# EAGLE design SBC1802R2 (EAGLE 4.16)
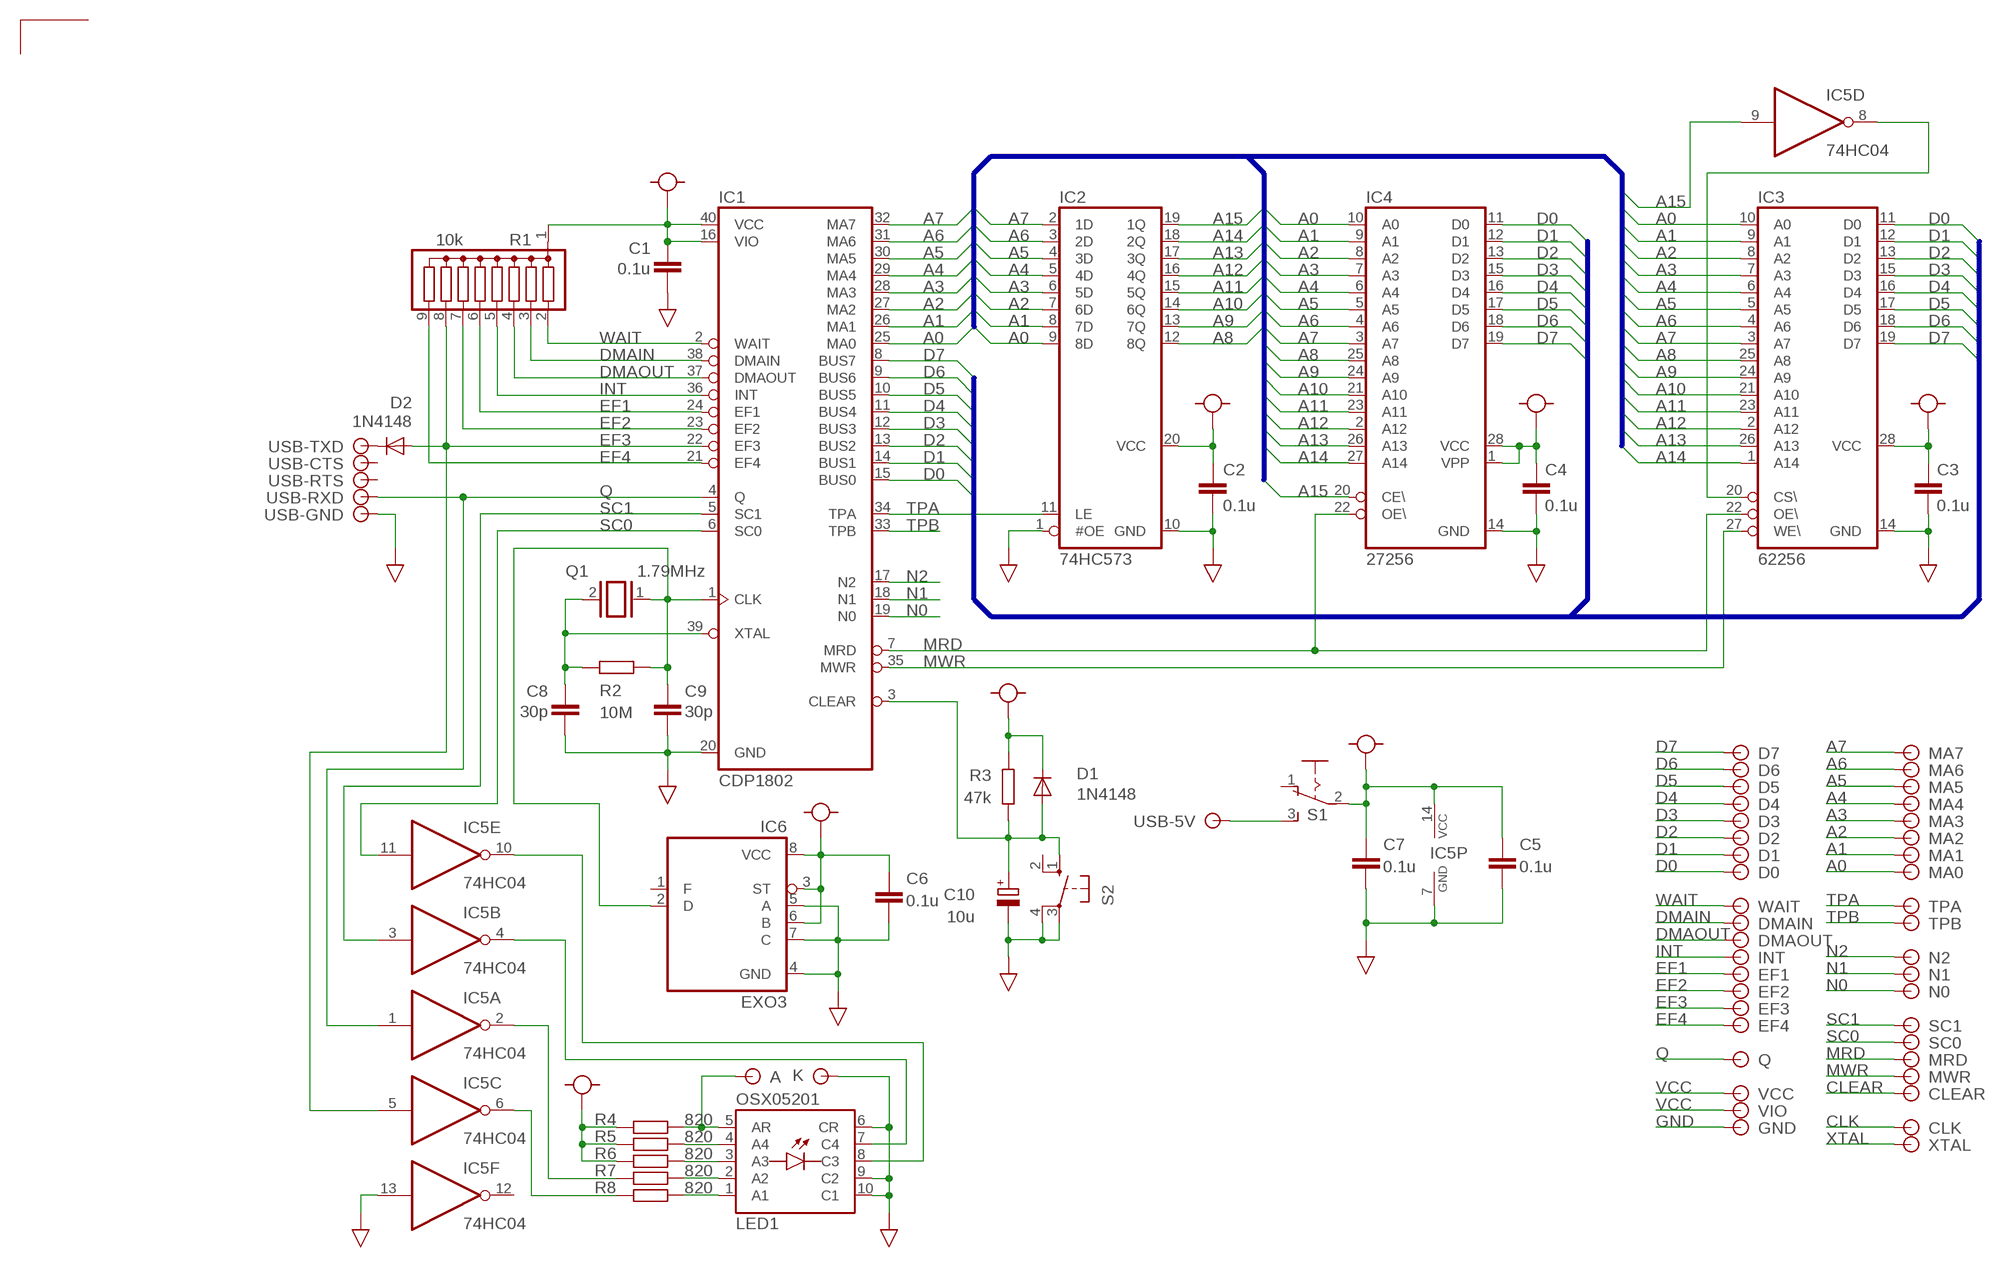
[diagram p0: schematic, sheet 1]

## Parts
C1  0.1u  C-CERAMIC  [C025-025X050]
C2  0.1u  C-CERAMIC  [C025-025X050]
C3  0.1u  C-CERAMIC  [C025-025X050]
C4  0.1u  C-CERAMIC  [C025-025X050]
C5  0.1u  C-CERAMIC  [C025-025X050]
C6  0.1u  C-CERAMIC  [C025-025X050]
C7  0.1u  C-CERAMIC  [C025-025X050]
C8  30p  C-CERAMIC  [C025-025X050]
C9  30p  C-CERAMIC  [C025-025X050]
C10  10u  C-TANTALUM  [C4518]
D1  1N4148  1S1588  [DO41-10]
D2  1N4148  1S1588  [DO41-10]
IC1  CDP1802  [DIL40]
IC2  74HC573  [DIL20]
IC3  62256  62256P  [DIL28]
IC4  27256  27256P  [DIL28]
IC5  74HC04  7404  [DIL14]
IC6  EXO3  EXO-3  [DIL08R]
LED1  OSX05201  OSX05201-GGR1  [OSX05201-GGR1]
Q1  1.79MHz  XTAL/S  [QS]
R1  10k  G08R  [SIL9]
R2  10M  R1/8W  [0207/10]
R3  47k  R1/8W  [0207/10]
R4  820  R1/8W  [0207/10]
R5  820  R1/8W  [0207/10]
R6  820  R1/8W  [0207/10]
R7  820  R1/8W  [0207/10]
R8  820  R1/8W  [0207/10]
S1  255SB  [255SB]
S2  SW-TACT  [B3F-10XX]
U$1  D7  LAND-NN-N  [LAND-NN-N]
U$2  MA7  LAND-NN-N  [LAND-NN-N]
U$3  D6  LAND-NN-N  [LAND-NN-N]
U$4  MA6  LAND-NN-N  [LAND-NN-N]
U$5  D5  LAND-NN-N  [LAND-NN-N]
U$6  MA5  LAND-NN-N  [LAND-NN-N]
U$7  D4  LAND-NN-N  [LAND-NN-N]
U$8  MA4  LAND-NN-N  [LAND-NN-N]
U$9  D3  LAND-NN-N  [LAND-NN-N]
U$10  MA3  LAND-NN-N  [LAND-NN-N]
U$11  D2  LAND-NN-N  [LAND-NN-N]
U$12  MA2  LAND-NN-N  [LAND-NN-N]
U$13  D1  LAND-NN-N  [LAND-NN-N]
U$14  MA1  LAND-NN-N  [LAND-NN-N]
U$15  D0  LAND-NN-N  [LAND-NN-N]
U$16  MA0  LAND-NN-N  [LAND-NN-N]
U$17  A  LAND-NN-N  [LAND-NN-N]
U$18  K  LAND-NN-N  [LAND-NN-N]
U$19  WAIT  LAND-NN-N  [LAND-NN-N]
U$20  TPA  LAND-NN-N  [LAND-NN-N]
U$21  DMAIN  LAND-NN-N  [LAND-NN-N]
U$22  TPB  LAND-NN-N  [LAND-NN-N]
U$23  DMAOUT  LAND-NN-N  [LAND-NN-N]
U$24  INT  LAND-NN-N  [LAND-NN-N]
U$25  N2  LAND-NN-N  [LAND-NN-N]
U$26  EF1  LAND-NN-N  [LAND-NN-N]
U$27  N1  LAND-NN-N  [LAND-NN-N]
U$28  EF2  LAND-NN-N  [LAND-NN-N]
U$29  N0  LAND-NN-N  [LAND-NN-N]
U$30  EF3  LAND-NN-N  [LAND-NN-N]
U$31  EF4  LAND-NN-N  [LAND-NN-N]
U$32  SC1  LAND-NN-N  [LAND-NN-N]
U$33  SC0  LAND-NN-N  [LAND-NN-N]
U$34  Q  LAND-NN-N  [LAND-NN-N]
U$35  MRD  LAND-NN-N  [LAND-NN-N]
U$36  MWR  LAND-NN-N  [LAND-NN-N]
U$37  VCC  LAND-NN-N  [LAND-NN-N]
U$38  CLEAR  LAND-NN-N  [LAND-NN-N]
U$39  VIO  LAND-NN-N  [LAND-NN-N]
U$40  GND  LAND-NN-N  [LAND-NN-N]
U$41  CLK  LAND-NN-N  [LAND-NN-N]
U$42  XTAL  LAND-NN-N  [LAND-NN-N]
USB-  TTL-232R-5V  [TTL-232R-5V]

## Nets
A0: IC1.25(MA0) IC2.9(8D) IC3.10(A0) IC4.10(A0) U$16.P
A1: IC1.26(MA1) IC2.8(7D) IC3.9(A1) IC4.9(A1) U$14.P
A2: IC1.27(MA2) IC2.7(6D) IC3.8(A2) IC4.8(A2) U$12.P
A3: IC1.28(MA3) IC2.6(5D) IC3.7(A3) IC4.7(A3) U$10.P
A4: IC1.29(MA4) IC2.5(4D) IC3.6(A4) IC4.6(A4) U$8.P
A5: IC1.30(MA5) IC2.4(3D) IC3.5(A5) IC4.5(A5) U$6.P
A6: IC1.31(MA6) IC2.3(2D) IC3.4(A6) IC4.4(A6) U$4.P
A7: IC1.32(MA7) IC2.2(1D) IC3.3(A7) IC4.3(A7) U$2.P
A8: IC2.12(8Q) IC3.25(A8) IC4.25(A8)
A9: IC2.13(7Q) IC3.24(A9) IC4.24(A9)
A10: IC2.14(6Q) IC3.21(A10) IC4.21(A10)
A11: IC2.15(5Q) IC3.23(A11) IC4.23(A11)
A12: IC2.16(4Q) IC3.2(A12) IC4.2(A12)
A13: IC2.17(3Q) IC3.26(A13) IC4.26(A13)
A14: IC2.18(2Q) IC3.1(A14) IC4.27(A14)
A15: IC2.19(1Q) IC4.20(CE\) IC5.9(D:I)
CLEAR: C10.+ D1.A IC1.3(CLEAR) R3.2 S2.1(S) U$38.P
CLK: C9.1 IC1.1(CLK) IC6.2(D) Q1.1 R2.2 U$41.P
D0: IC1.15(BUS0) IC3.11(D0) IC4.11(D0) U$15.P
D1: IC1.14(BUS1) IC3.12(D1) IC4.12(D1) U$13.P
D2: IC1.13(BUS2) IC3.13(D2) IC4.13(D2) U$11.P
D3: IC1.12(BUS3) IC3.15(D3) IC4.15(D3) U$9.P
D4: IC1.11(BUS4) IC3.16(D4) IC4.16(D4) U$7.P
D5: IC1.10(BUS5) IC3.17(D5) IC4.17(D5) U$5.P
D6: IC1.9(BUS6) IC3.18(D6) IC4.18(D6) U$3.P
D7: IC1.8(BUS7) IC3.19(D7) IC4.19(D7) U$1.P
DMAIN: IC1.38(DMAIN) R1.3 U$21.P
DMAOUT: IC1.37(DMAOUT) R1.4 U$23.P
EF1: IC1.24(EF1) R1.6 U$26.P
EF2: IC1.23(EF2) R1.7 U$28.P
EF3: D2.A IC1.22(EF3) IC5.5(C:I) R1.8 U$30.P
EF4: IC1.21(EF4) R1.9 U$31.P
GND: C1.2 C2.2 C3.2 C4.2 C5.2 C6.2 C7.2 C8.2 C9.2 C10.- IC1.20(GND) IC2.1(#OE) IC2.10(GND) IC3.14(GND) IC4.14(GND) IC5.7(P:GND) IC5.13(F:I) IC6.4(GND) IC6.5(A) IC6.7(C) LED1.6(CR) LED1.9(C2) LED1.10(C1) S2.3(P) S2.4(P1) U$18.P U$40.P USB-.1
INT: IC1.36(INT) R1.5 U$24.P
MRD: IC1.7(MRD) IC3.22(OE\) IC4.22(OE\) U$35.P
MWR: IC1.35(MWR) IC3.27(WE\) U$36.P
N0: IC1.19(N0) U$29.P
N1: IC1.18(N1) U$27.P
N2: IC1.17(N2) U$25.P
N$1: S1.3(S) USB-.3
N$2: LED1.5(AR) R4.2 U$17.P
N$3: IC5.6(C:O) R8.1
N$4: IC5.2(A:O) R7.1
N$5: IC5.10(E:O) LED1.8(C3)
N$6: IC5.4(B:O) LED1.7(C4)
N$7: LED1.4(A4) R5.2
N$8: LED1.3(A3) R6.2
N$9: D2.C USB-.4
N$13: IC3.20(CS\) IC5.8(D:O)
N$16: LED1.1(A1) R8.2
N$17: LED1.2(A2) R7.2
Q: IC1.4(Q) IC5.1(A:I) U$34.P USB-.5
SC0: IC1.6(SC0) IC5.11(E:I) U$33.P
SC1: IC1.5(SC1) IC5.3(B:I) U$32.P
TPA: IC1.34(TPA) IC2.11(LE) U$20.P
TPB: IC1.33(TPB) U$22.P
VCC: C1.1 C2.1 C3.1 C4.1 C5.1 C6.1 C7.1 D1.C IC1.16(VIO) IC1.40(VCC) IC2.20(VCC) IC3.28(VCC) IC4.1(VPP) IC4.28(VCC) IC5.14(P:VCC) IC6.3(ST) IC6.6(B) IC6.8(VCC) R1.1 R3.1 R4.1 R5.1 R6.1 S1.2(P) U$37.P U$39.P
WAIT: IC1.2(WAIT) R1.2 U$19.P
XTAL: C8.1 IC1.39(XTAL) Q1.2 R2.1 U$42.P
Unconnected: IC5.12(F:O) IC6.1(F) S1.1(O) S2.2(S1) USB-.2 USB-.6

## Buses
A[0..15]
D[0..7]

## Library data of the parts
C1-C9 = olimex-devices:C-CERAMIC: Ceramic Conenser
C10 = olimex-devices:C-TANTALUM: Tantalum Condenser
D1 D2 = olimex-devices:1S1588: Small Signal Diode
IC1 = olimex-devices:CDP1802
IC2 = olimex-devices:74HC573
IC3 = olimex-devices:62256P
IC4 = olimex-devices:27256P
IC5 = olimex-devices:7404: Hex INVERTER
IC6 = olimex-devices:EXO-3
LED1 = olimex-devices:OSX05201-GGR1
Q1 = olimex-devices:XTAL/S: X'tal Oscirator
R1 = olimex-devices:G08R: SIL RESISTOR
R2-R8 = olimex-devices:R1/8W: Carbon Resistor
S1 = olimex-devices:255SB: SLIDING SWITCH distributor Buerklin, 11G810
S2 = olimex-devices:SW-TACT: Tact Switch (Small)
U$1-U$42 = olimex-devices:LAND-NN-N
USB- = olimex-devices:TTL-232R-5V

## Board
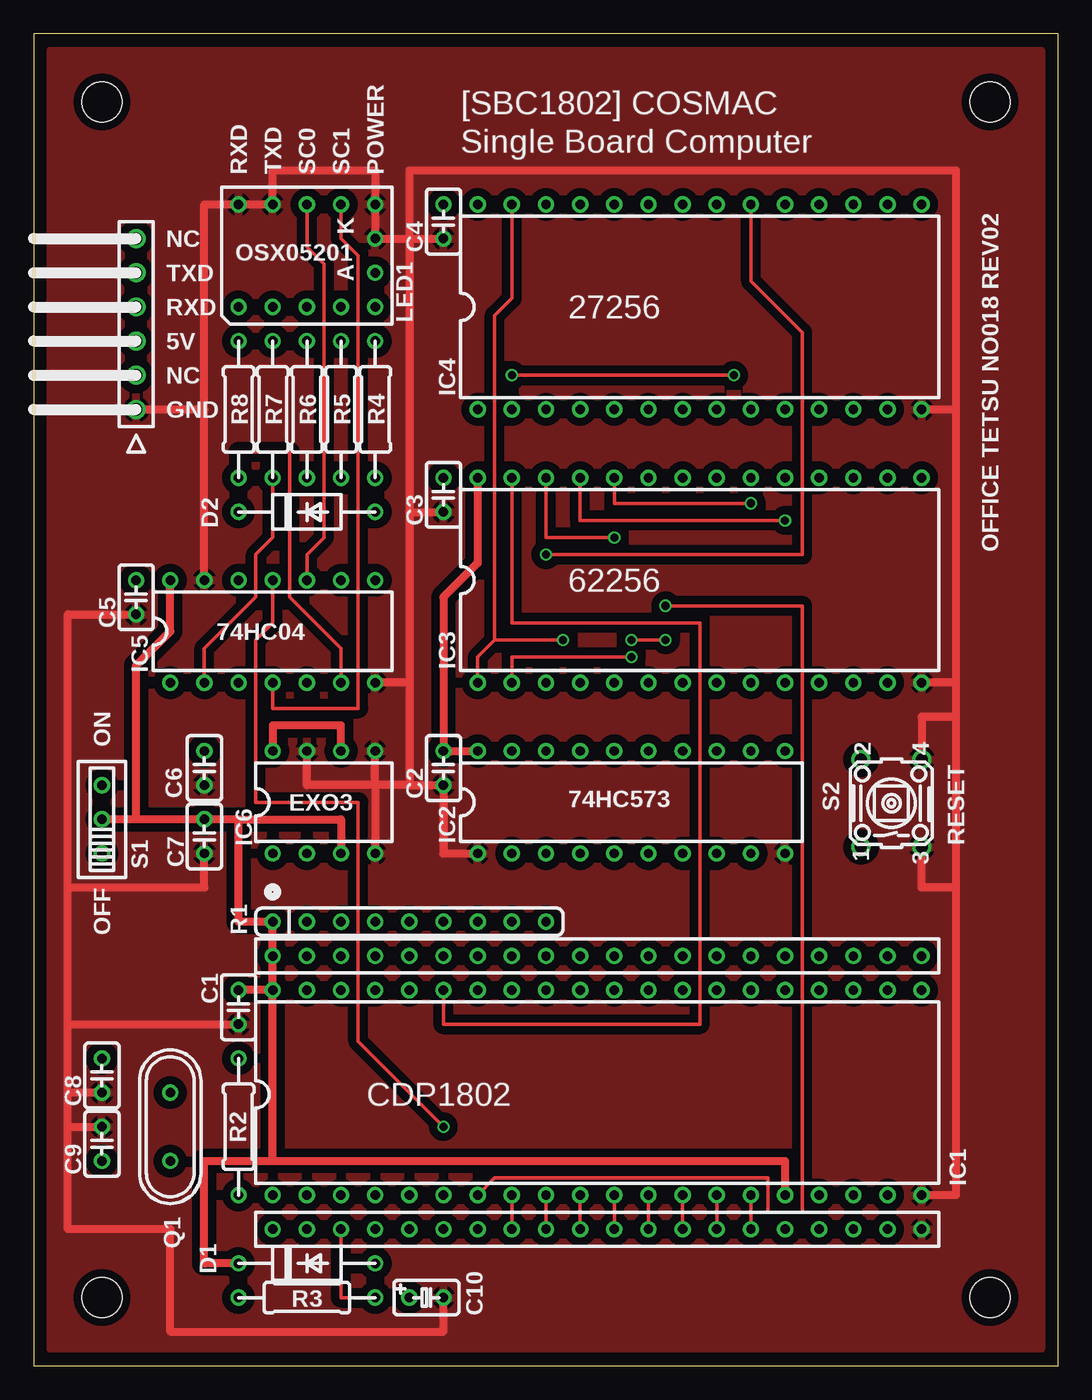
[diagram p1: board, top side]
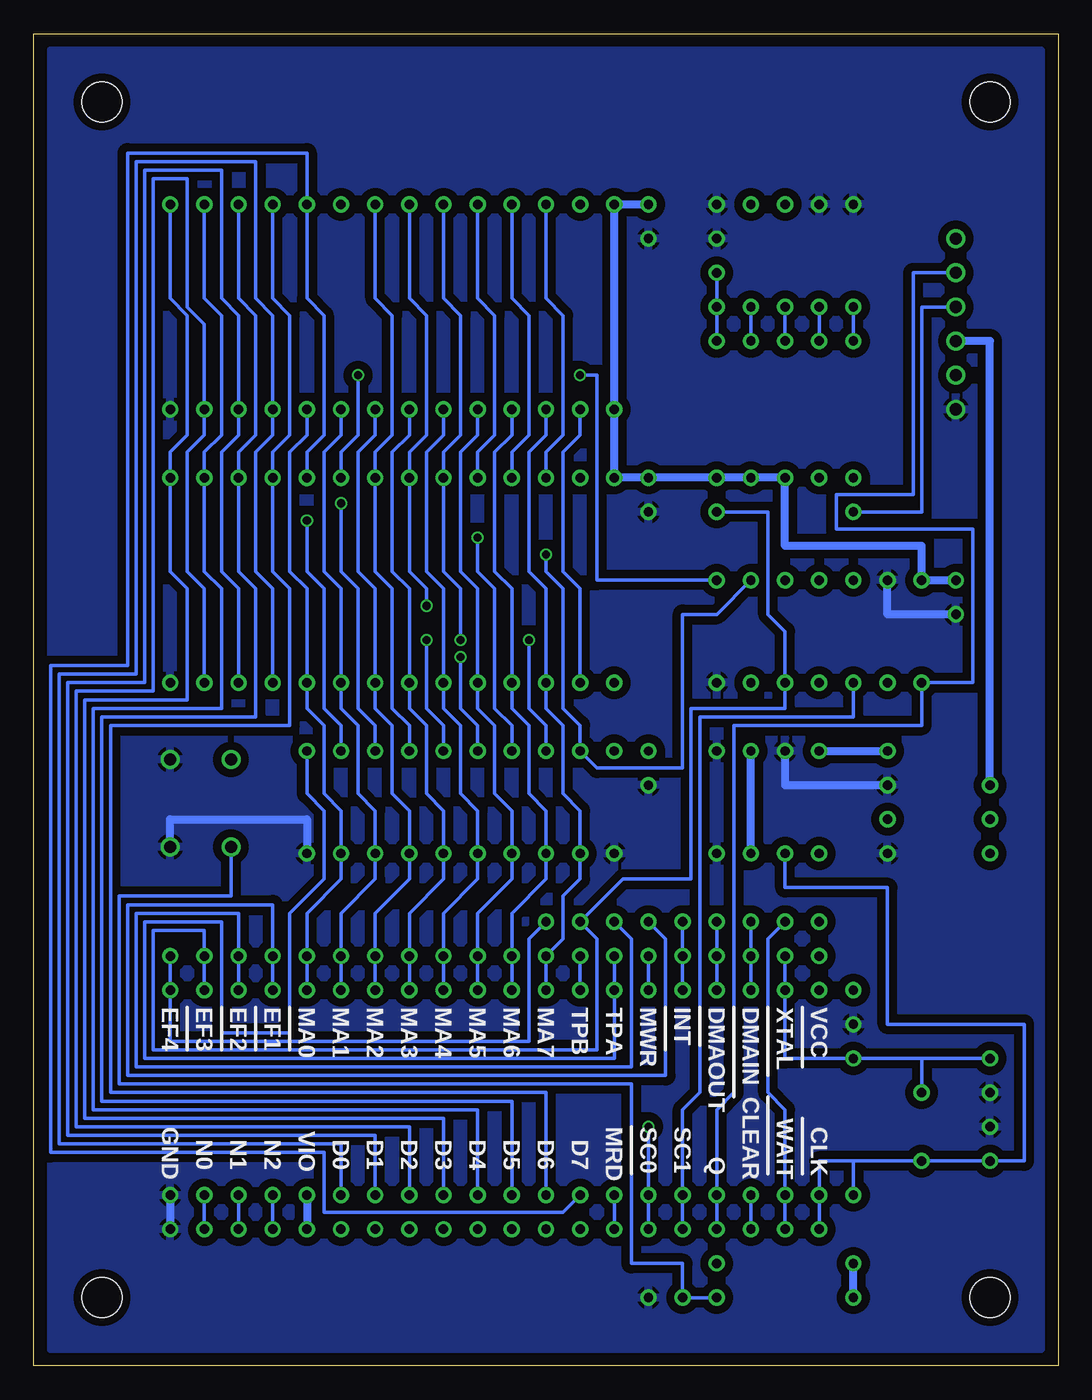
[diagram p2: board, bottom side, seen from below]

Size 76.2 x 99.06 mm. Coordinates in mm from the lower left corner, seen from the top.
Outline: 76.2,0 76.2,99.06 0,99.06 0,0 76.2,0
Copper layers (1*16): Top 0.035mm / dielectric 1.5mm / Bottom 0.035mm
Design rules "OfficeTETSUstandard": minimum track width 6mil, minimum drill 12mil, track to track 6mil, track to pad 6mil, pad to pad 6mil, via to via 6mil, smd to smd 0mil, copper to edge 10mil, drill to drill 10mil, minimum pad ring 10mil, minimum via ring 6mil, stop-mask expansion 2mil, vias tented up to drill 25mil, thermal gap 10mil
Holes 3 mm at 71.12,93.98 5.08,93.98 71.12,5.08 5.08,5.08

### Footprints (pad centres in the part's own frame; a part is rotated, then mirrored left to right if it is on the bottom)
C025-025X050 = drill 0.7 round: 1 -1.27,0; 2 1.27,0
C4518 = drill 0.7 round: + -1.27,0; - 1.27,0
DO41-10 = drill 0.7 round: A 5.08,0; C -5.08,0
DIL40 = drill 0.7 round: 1 -24.13,-7.62; 2 -21.59,-7.62; 3 -19.05,-7.62; 4 -16.51,-7.62; 5 -13.97,-7.62; 6 -11.43,-7.62; 7 -8.89,-7.62; 8 -6.35,-7.62; 9 -3.81,-7.62; 10 -1.27,-7.62; 11 1.27,-7.62; 12 3.81,-7.62; 13 6.35,-7.62; 14 8.89,-7.62; 15 11.43,-7.62; 16 13.97,-7.62; 17 16.51,-7.62; 18 19.05,-7.62; 19 21.59,-7.62; 20 24.13,-7.62; 21 24.13,7.62; 22 21.59,7.62; 23 19.05,7.62; 24 16.51,7.62; 25 13.97,7.62; 26 11.43,7.62; 27 8.89,7.62; 28 6.35,7.62; 29 3.81,7.62; 30 1.27,7.62; 31 -1.27,7.62; 32 -3.81,7.62; 33 -6.35,7.62; 34 -8.89,7.62; 35 -11.43,7.62; 36 -13.97,7.62; 37 -16.51,7.62; 38 -19.05,7.62; 39 -21.59,7.62; 40 -24.13,7.62
DIL20 = drill 0.7 round: 1 -11.43,-3.81; 2 -8.89,-3.81; 3 -6.35,-3.81; 4 -3.81,-3.81; 5 -1.27,-3.81; 6 1.27,-3.81; 7 3.81,-3.81; 8 6.35,-3.81; 9 8.89,-3.81; 10 11.43,-3.81; 11 11.43,3.81; 12 8.89,3.81; 13 6.35,3.81; 14 3.81,3.81; 15 1.27,3.81; 16 -1.27,3.81; 17 -3.81,3.81; 18 -6.35,3.81; 19 -8.89,3.81; 20 -11.43,3.81
DIL28 = drill 0.7 round: 1 -16.51,-7.62; 2 -13.97,-7.62; 3 -11.43,-7.62; 4 -8.89,-7.62; 5 -6.35,-7.62; 6 -3.81,-7.62; 7 -1.27,-7.62; 8 1.27,-7.62; 9 3.81,-7.62; 10 6.35,-7.62; 11 8.89,-7.62; 12 11.43,-7.62; 13 13.97,-7.62; 14 16.51,-7.62; 15 16.51,7.62; 16 13.97,7.62; 17 11.43,7.62; 18 8.89,7.62; 19 6.35,7.62; 20 3.81,7.62; 21 1.27,7.62; 22 -1.27,7.62; 23 -3.81,7.62; 24 -6.35,7.62; 25 -8.89,7.62; 26 -11.43,7.62; 27 -13.97,7.62; 28 -16.51,7.62
DIL14 = drill 0.7 round: 1 -7.62,-3.81; 2 -5.08,-3.81; 3 -2.54,-3.81; 4 0,-3.81; 5 2.54,-3.81; 6 5.08,-3.81; 7 7.62,-3.81; 8 7.62,3.81; 9 5.08,3.81; 10 2.54,3.81; 11 0,3.81; 12 -2.54,3.81; 13 -5.08,3.81; 14 -7.62,3.81
DIL08R = drill 0.7 round: 1 -3.81,-3.81; 2 -1.27,-3.81; 3 1.27,-3.81; 4 3.81,-3.81; 5 3.81,3.81; 6 1.27,3.81; 7 -1.27,3.81; 8 -3.81,3.81
OSX05201-GGR1 = drill 0.7 round: 1 -5.08,-3.81; 2 -2.54,-3.81; 3 0,-3.81; 4 2.54,-3.81; 5 5.08,-3.81; 6 5.08,3.81; 7 2.54,3.81; 8 0,3.81; 9 -2.54,3.81; 10 -5.08,3.81
QS = drill 0.7 round: 1 -2.54,0; 2 2.54,0
SIL9 = drill 0.7 round: 1 -10.16,0; 2 -7.62,0; 3 -5.08,0; 4 -2.54,0; 5 0,0; 6 2.54,0; 7 5.08,0; 8 7.62,0; 9 10.16,0
0207/10 = drill 0.7 round: 1 -5.08,0; 2 5.08,0
255SB = drill 0.7 round: 1 -2.54,0; 2 0,0; 3 2.54,0
B3F-10XX = drill 0.9 round: 1 -3.251,2.261; 2 3.251,2.261; 3 -3.251,-2.261; 4 3.251,-2.261
LAND-NN-N = drill 0.7 round: P 0,0
TTL-232R-5V = drill 0.9 round: 1 -6.35,0; 2 -3.81,0; 3 -1.27,0; 4 1.27,0; 5 3.81,0; 6 6.35,0

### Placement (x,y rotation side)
C1  15.24,26.67 270 top
C2  30.48,44.45 270 top
C3  30.48,64.77 270 top
C4  30.48,85.09 270 top
C5  7.62,57.15 270 top
C6  12.7,44.45 270 top
C7  12.7,39.37 270 top
C8  5.08,21.59 270 top
C9  5.08,16.51 90 top
C10  29.21,5.08 0 top
D1  20.32,7.62 0 top
D2  20.32,63.5 0 top
IC1  41.91,20.32 0 top
IC2  44.45,41.91 0 top
IC3  49.53,58.42 0 top
IC4  49.53,78.74 0 top
IC5  17.78,54.61 0 top
IC6  21.59,41.91 0 top
LED1  20.32,82.55 0 top
Q1  10.16,17.78 90 top
R1  27.94,33.02 0 top
R2  15.24,17.78 270 top
R3  20.32,5.08 0 top
R4  25.4,71.12 90 top
R5  22.86,71.12 90 top
R6  20.32,71.12 90 top
R7  17.78,71.12 90 top
R8  15.24,71.12 90 top
S1  5.08,40.64 90 top
S2  63.79,41.84 90 top
U$1  35.56,10.16 90 top
U$2  38.1,30.48 270 top
U$3  38.1,10.16 90 top
U$4  40.64,30.48 270 top
U$5  40.64,10.16 90 top
U$6  43.18,30.48 270 top
U$7  43.18,10.16 90 top
U$8  45.72,30.48 270 top
U$9  45.72,10.16 90 top
U$10  48.26,30.48 270 top
U$11  48.26,10.16 90 top
U$12  50.8,30.48 270 top
U$13  50.8,10.16 90 top
U$14  53.34,30.48 270 top
U$15  53.34,10.16 90 top
U$16  55.88,30.48 270 top
U$17  25.4,81.28 0 top
U$18  25.4,83.82 0 top
U$19  20.32,10.16 90 top
U$20  33.02,30.48 270 top
U$21  22.86,30.48 270 top
U$22  35.56,30.48 270 top
U$23  25.4,30.48 270 top
U$24  27.94,30.48 270 top
U$25  58.42,10.16 90 top
U$26  58.42,30.48 270 top
U$27  60.96,10.16 90 top
U$28  60.96,30.48 270 top
U$29  63.5,10.16 90 top
U$30  63.5,30.48 270 top
U$31  66.04,30.48 270 top
U$32  27.94,10.16 90 top
U$33  30.48,10.16 90 top
U$34  25.4,10.16 90 top
U$35  33.02,10.16 90 top
U$36  30.48,30.48 270 top
U$37  17.78,30.48 270 top
U$38  22.86,10.16 90 top
U$39  55.88,10.16 90 top
U$40  66.04,10.16 90 top
U$41  17.78,10.16 90 top
U$42  20.32,30.48 270 top
USB-  7.62,77.47 90 top

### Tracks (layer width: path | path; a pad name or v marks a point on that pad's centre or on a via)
A0
  Bottom 0.254: IC4.10 55.88,69.22 57.15,67.94 57.15,59.05 55.88,57.78 IC3.10 55.88,48.9 54.61,47.62 54.61,42.55 53.34,41.27 IC2.9 53.34,36.2 55.88,33.66 U$16.P IC1.25
A1
  Bottom 0.254: IC4.9 53.34,69.22 54.61,67.94 54.61,59.05 53.34,57.78 IC3.9 53.34,48.9 52.07,47.62 52.07,42.55 50.8,41.27 IC2.8 50.8,36.2 53.34,33.66 IC1.26 U$14.P
A2
  Bottom 0.254: IC4.8 50.8,69.22 52.07,67.94 52.07,59.05 50.8,57.78 IC3.8 50.8,48.9 49.53,47.62 49.53,42.55 48.26,41.27 IC2.7 48.26,36.2 50.8,33.66 U$12.P IC1.27
A3
  Bottom 0.254: IC4.7 48.26,69.22 49.53,67.94 49.53,59.05 48.26,57.78 IC3.7 48.26,48.9 46.99,47.62 46.99,42.55 45.72,41.27 IC2.6 45.72,36.2 48.26,33.66 U$10.P IC1.28
A4
  Bottom 0.254: IC4.6 45.72,69.22 46.99,67.94 46.99,59.05 45.72,57.78 IC3.6 45.72,48.9 44.45,47.62 44.45,42.55 43.18,41.27 IC2.5 43.18,36.2 45.72,33.66 IC1.29 U$8.P
A5
  Bottom 0.254: IC4.5 43.18,69.22 44.45,67.94 44.45,59.05 43.18,57.78 IC3.5 43.18,48.9 41.91,47.62 41.91,42.55 40.64,41.27 IC2.4 40.64,36.2 43.18,33.66 U$6.P IC1.30
A6
  Bottom 0.254: IC4.4 40.64,69.22 41.91,67.94 41.91,59.05 40.64,57.78 IC3.4 40.64,48.9 39.37,47.62 39.37,42.55 38.1,41.27 IC2.3 38.1,36.2 40.64,33.66 U$4.P IC1.31
A7
  Bottom 0.254: IC4.3 38.1,69.22 39.37,67.94 39.37,59.05 38.1,57.78 IC3.3 38.1,48.9 36.83,47.62 36.83,42.55 35.56,41.27 IC2.2 35.56,36.2 36.83,34.92 36.83,31.75 U$2.P IC1.32
A8  (via drill 0.6)
  Top 0.254: v55.88,62.87 40.64,62.87 IC3.25
  Bottom 0.254: IC3.25 40.64,67.94 39.37,69.22 39.37,78.11 40.64,79.38 IC4.25 | IC2.12 53.34,47.62 54.61,48.9 54.61,57.78 55.88,59.05 v55.88,62.87
A9  (via drill 0.6)
  Top 0.254: v53.34,64.14 43.18,64.14 IC3.24
  Bottom 0.254: IC3.24 43.18,67.94 41.91,69.22 41.91,78.11 43.18,79.38 IC4.24 | IC2.13 50.8,47.62 52.07,48.9 52.07,57.78 53.34,59.05 v53.34,64.14
A10
  Bottom 0.254: IC4.21 50.8,79.38 49.53,78.11 49.53,69.22 50.8,67.94 IC3.21 50.8,59.05 49.53,57.78 49.53,48.9 48.26,47.62 IC2.14
A11  (via drill 0.6)
  Top 0.254: v46.99,53.98 v44.45,53.98
  Bottom 0.254: IC4.23 45.72,79.38 44.45,78.11 44.45,69.22 45.72,67.94 IC3.23 45.72,59.05 44.45,57.78 v44.45,53.98 | v46.99,53.98 46.99,48.9 45.72,47.62 IC2.15
A12  (via drill 0.6)
  Top 0.254: v44.45,52.7 35.56,52.7 IC3.2
  Bottom 0.254: IC3.2 35.56,57.78 36.83,59.05 36.83,67.94 35.56,69.22 IC4.2 | IC2.16 43.18,47.62 44.45,48.9 v44.45,52.7
A13  (via drill 0.6)
  Top 0.254: v43.18,61.59 38.1,61.59 IC3.26
  Bottom 0.254: IC3.26 38.1,67.94 36.83,69.22 36.83,78.11 38.1,79.38 IC4.26 | IC2.17 40.64,47.62 41.91,48.9 41.91,57.78 43.18,59.05 v43.18,61.59
A14  (via drill 0.6)
  Top 0.254: v39.37,53.98 34.29,53.98 | 34.29,53.98 33.02,52.7 IC3.1 | IC4.27 35.56,79.38 34.29,78.11 34.29,53.98
  Bottom 0.254: IC2.18 38.1,47.62 39.37,48.9 v39.37,53.98
A15  (via drill 0.6)
  Top 0.254: v38.1,60.33 57.15,60.33 57.15,76.83 53.34,80.64 IC4.20
  Bottom 0.254: v38.1,60.33 38.1,59.05 36.83,57.78 36.83,48.9 35.56,47.62 IC2.19 34.29,44.45 27.94,44.45 27.94,55.88 25.4,55.88 IC5.9
CLEAR
  Top 0.254: 22.86,7.62 U$38.P | 22.86,7.62 22.86,5.08 R3.2 | 22.86,7.62 D1.A
  Bottom 0.254: S2.1 61.53,34.92 69.85,34.92 69.85,20.95 31.75,20.95 31.75,7.62 27.94,7.62 C10.+ R3.2 | U$38.P IC1.3
CLK
  Bottom 0.254: U$41.P IC1.1 17.78,15.24 15.24,15.24 | 15.24,15.24 Q1.1 C9.1 2.54,15.24 2.54,25.4 12.7,25.4 12.7,35.56 20.32,35.56 IC6.2 | 15.24,15.24 R2.2
D0
  Top 0.254: U$15.P IC1.15
  Bottom 0.254: IC1.15 53.34,16.51 74.3,16.51 74.3,51.44 68.58,51.44 68.58,89.53 59.69,89.53 59.69,79.38 58.42,78.11 IC4.11 58.42,69.22 59.69,67.94 59.69,59.05 58.42,57.78 IC3.11
D1
  Top 0.254: U$13.P IC1.14
  Bottom 0.254: IC1.14 50.8,17.14 73.66,17.14 73.66,50.8 67.94,50.8 67.94,88.9 62.23,88.9 62.23,79.38 60.96,78.11 IC4.12 60.96,69.22 62.23,67.94 62.23,59.05 60.96,57.78 IC3.12
D2
  Top 0.254: U$11.P IC1.13
  Bottom 0.254: IC1.13 48.26,17.78 73.03,17.78 73.03,50.16 67.31,50.16 67.31,88.27 64.77,88.27 64.77,78.74 63.5,77.47 IC4.13 63.5,69.22 64.77,67.94 64.77,59.05 63.5,57.78 IC3.13
D3
  Top 0.254: U$9.P IC1.12
  Bottom 0.254: IC1.12 45.72,18.41 72.39,18.41 72.39,49.53 64.77,49.53 64.77,57.78 66.04,59.05 IC3.15 66.04,67.94 64.77,69.22 64.77,78.11 66.04,79.38 IC4.15
D4
  Top 0.254: U$7.P IC1.11
  Bottom 0.254: IC1.11 43.18,19.05 71.75,19.05 71.75,48.9 62.23,48.9 62.23,57.78 63.5,59.05 IC3.16 63.5,67.94 62.23,69.22 62.23,78.11 63.5,79.38 IC4.16
D5
  Top 0.254: U$5.P IC1.10
  Bottom 0.254: IC1.10 40.64,19.68 71.12,19.68 71.12,48.26 59.69,48.26 59.69,57.78 60.96,59.05 IC3.17 60.96,67.94 59.69,69.22 59.69,78.11 60.96,79.38 IC4.17
D6
  Top 0.254: U$3.P IC1.9
  Bottom 0.254: IC1.9 38.1,20.32 70.48,20.32 70.48,47.62 57.15,47.62 57.15,57.78 58.42,59.05 IC3.18 58.42,67.94 57.15,69.22 57.15,78.11 58.42,79.38 IC4.18
D7
  Top 0.254: U$1.P IC1.8
  Bottom 0.254: IC1.8 36.83,11.43 54.61,11.43 54.61,15.88 74.93,15.88 74.93,52.07 69.22,52.07 69.22,90.17 55.88,90.17 IC4.19 55.88,79.38 54.61,78.11 54.61,69.22 55.88,67.94 IC3.19
DMAIN
  Bottom 0.254: U$21.P IC1.38 R1.3
DMAOUT
  Bottom 0.254: U$23.P IC1.37 R1.4
EF1
  Bottom 0.254: R1.6 29.21,31.75 29.21,21.59 69.22,21.59 69.22,34.29 58.42,34.29 U$26.P IC1.24
EF2
  Bottom 0.254: R1.7 31.75,31.75 31.75,22.23 68.58,22.23 68.58,33.66 60.96,33.66 U$28.P IC1.23
EF3
  Bottom 0.254: IC1.22 U$30.P 63.5,32.38 67.31,32.38 67.31,23.5 34.29,23.5 34.29,31.75 R1.8 32.38,36.2 27.3,36.2 27.3,48.9 20.32,48.9 IC5.5 20.32,54.61 21.59,55.88 21.59,63.5 D2.A
EF4
  Bottom 0.254: R1.9 39.37,31.75 39.37,24.13 66.04,24.13 IC1.21 U$31.P
GND
  Top 0.61: IC1.20 68.58,12.7 68.58,35.56 | 68.58,48.26 68.58,35.56 | 68.58,50.8 68.58,48.26 | 68.58,71.12 68.58,50.8 | 68.58,71.12 IC4.14 | 68.58,50.8 IC3.14 | S2.4 66.05,48.26 68.58,48.26 | S2.3 66.05,35.56 68.58,35.56 | 2.54,20.32 C8.2 | 2.54,17.78 2.54,10.16 10.16,10.16 10.16,2.54 30.48,2.54 C10.- | 2.54,17.78 2.54,20.32 | C5.2 2.54,55.88 2.54,35.56 | IC2.1 30.48,38.1 C2.2 27.94,43.18 | 2.54,20.32 2.54,25.4 | 2.54,25.4 2.54,35.56 | 68.58,71.12 68.58,88.9 27.94,88.9 27.94,83.82 | 27.94,83.82 C4.2 | 27.94,50.8 IC5.7 | 27.94,50.8 27.94,43.18 | 27.94,83.82 U$18.P LED1.6 25.4,88.9 17.78,88.9 LED1.9 LED1.10 12.7,86.36 12.7,71.12 | 27.94,83.82 27.94,63.5 | 27.94,63.5 C3.2 | 27.94,63.5 27.94,50.8 | 2.54,17.78 C9.2 | 2.54,25.4 C1.2 | 12.7,71.12 USB-.1 | IC5.13 12.7,71.12 | 27.94,43.18 25.4,43.18 | 25.4,43.18 20.32,43.18 IC6.7 | 25.4,43.18 IC6.5 | 25.4,43.18 IC6.4 | C7.2 12.7,35.56 2.54,35.56
  Bottom 0.61: IC2.10 55.88,40.64 66.05,40.64 S2.3 | IC1.20 U$40.P | C5.2 12.7,55.88 IC5.13 | C6.2 20.32,43.18 IC6.7
  pour Bottom (isolate 0.61): 1.27,97.79 74.93,97.79 74.93,1.27 1.27,1.27
  pour Top (isolate 0.61): 1.27,97.79 74.93,97.79 74.93,1.27 1.27,1.27
INT
  Bottom 0.254: U$24.P IC1.36 R1.5
MRD  (via drill 0.6)
  Top 0.254: v46.99,56.52 57.15,56.52 57.15,11.43 54.61,11.43 54.61,13.97 34.29,13.97 IC1.7
  Bottom 0.254: IC4.22 48.26,79.38 46.99,78.11 46.99,69.22 48.26,67.94 IC3.22 48.26,59.05 46.99,57.78 v46.99,56.52 | U$35.P IC1.7
MWR
  Top 0.254: IC3.27 35.56,55.24 49.53,55.24 49.53,25.4 30.48,25.4 IC1.35
  Bottom 0.254: IC1.35 U$36.P
N0
  Bottom 0.254: U$29.P IC1.19
N1
  Bottom 0.254: U$27.P IC1.18
N2
  Bottom 0.254: U$25.P IC1.17
N$1
  Bottom 0.61: USB-.3 5.08,76.2 S1.3
N$2
  Bottom 0.254: R4.2 LED1.5 U$17.P
N$3
  Top 0.254: IC5.6 22.86,53.34 19.05,57.15 19.05,67.94 15.24,67.94 R8.1
N$4
  Top 0.254: IC5.2 12.7,53.34 16.51,57.15 16.51,60.33 17.78,61.59 R7.1
N$5
  Top 0.254: IC5.10 20.32,60.33 21.59,61.59 21.59,81.92 20.32,83.19 LED1.8
N$6
  Top 0.254: IC5.4 17.78,48.9 24.13,48.9 24.13,82.55 22.86,83.82 LED1.7
N$7
  Bottom 0.254: R5.2 LED1.4
N$8
  Bottom 0.254: R6.2 LED1.3
N$9
  Bottom 0.254: USB-.4 10.16,78.74 10.16,63.5 D2.C
N$13  (via drill 0.6)
  Top 0.254: v35.56,73.66 v52.07,73.66
  Bottom 0.254: IC5.8 34.29,58.42 34.29,73.66 v35.56,73.66 | v52.07,73.66 52.07,69.22 53.34,67.94 IC3.20
N$16
  Bottom 0.254: R8.2 LED1.1
N$17
  Bottom 0.254: R7.2 LED1.2
Q
  Bottom 0.254: U$34.P IC1.4 25.4,19.05 24.13,20.32 24.13,47.62 10.16,47.62 IC5.1 6.35,50.8 6.35,62.23 16.51,62.23 16.51,64.77 10.79,64.77 10.79,81.28 USB-.5
SC0  (via drill 0.6)
  Top 0.254: v30.48,17.78 24.13,24.13 24.13,41.91 16.51,41.91 16.51,53.98 17.78,55.24 IC5.11
  Bottom 0.254: U$33.P IC1.6 v30.48,17.78
SC1
  Bottom 0.254: U$32.P IC1.5 27.94,19.05 26.67,20.32 26.67,48.26 15.24,48.26 IC5.3
TPA
  Bottom 0.254: IC2.11 55.88,42.55 54.61,41.27 54.61,36.2 57.15,33.66 57.15,24.77 62.23,24.77 62.23,33.02 67.94,33.02 67.94,22.86 33.02,22.86 IC1.34 U$20.P
TPB
  Bottom 0.254: IC1.33 U$22.P
VCC
  Top 0.61: IC1.40 C1.1 | IC1.40 U$37.P R1.1 15.24,33.02 15.24,40.64 | D1.C 12.7,7.62 12.7,15.24 17.78,15.24 | 17.78,15.24 IC1.40 | IC3.28 33.02,59.69 30.48,57.15 C2.1 IC2.20 | 7.62,40.64 7.62,52.07 10.16,54.61 IC5.14 | IC1.16 55.88,15.24 17.78,15.24 | IC6.8 17.78,47.62 22.86,47.62 IC6.6 | IC6.3 22.86,40.64 15.24,40.64 | 7.62,40.64 S1.2 | 7.62,40.64 C7.1 15.24,40.64
  Bottom 0.61: IC1.16 U$39.P | R3.1 D1.C | C5.1 IC5.14 10.16,60.96 20.32,60.96 R6.1 R5.1 R4.1 C3.1 IC3.28 IC4.1 IC4.28 C4.1 | IC6.3 IC6.6 | IC6.8 C6.1
WAIT
  Bottom 0.254: U$19.P IC1.2 20.32,19.05 21.59,20.32 21.59,31.75 R1.2
XTAL
  Bottom 0.254: U$42.P IC1.39 20.32,22.86 R2.1 10.16,22.86 | C8.1 10.16,22.86 | 10.16,22.86 Q1.2

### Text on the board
tPlace: [SBC1802] COSMAC | Single Board Computer | RXD | TXD | SC0 | SC1 | POWER | OFFICE TETSU NO018 REV02 | NC | TXD | RXD | 5V | NC | GND | ON | RESET | OFF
